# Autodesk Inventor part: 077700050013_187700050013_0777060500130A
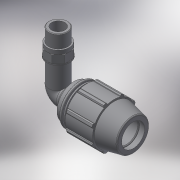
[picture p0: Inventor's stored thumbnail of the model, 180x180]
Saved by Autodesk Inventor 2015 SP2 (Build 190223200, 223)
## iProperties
Created: 2017-02
Part Number: 077700050013_187700050013_0777060500130A
Material: Generic
Description: PLASSON 90° ELBOW MALE WITH INTEGRAL BRASS THREAD 50-1.1/4"
Document SubType Name: Modeling
Designer: KIM
Mass: 174.249 g
Surface Area: 431.906 cm^2
Volume: 174.249 cm^3
Density: 1 g/cm^3
Appearance: Default
Author: KIM
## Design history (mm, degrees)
derived "07770.ipt"
feature "Solid1::07770.ipt"
tag "TaggingFeature1"
body "Solid1"
other parameters: "d4" = 12, "d5" = 36, "d7" = 96, "d9" = 20.57143, "d11" = 4.8, "d13" = 120 deg, "d15" = 12 deg, "d16" = 83.52, "d18" = 2.5, "d19" = 35 deg, "d20" = 17.5 deg, "d21" = 89.28, "d23" = 0, "d25" = 360 deg, "d27" = 1.92, "d33" = 1, "d42" = 53.28, "d43" = 2.88, "d46" = 1.5, "d51" = 144, "d68" = 9.6, "d72" = 97, "d73" = 41.91, "d74" = 22, "d75" = 48.1965, "d76" = 29.337, "d79" = 16.764, "d80" = 1.2573, "d83" = 0, "d84" = 0, "d91" = 72, "d93" = 93, "d94" = 41.91, "d95" = 29.337, "d96" = 9.6, "d97" = 50 deg, "d98" = 2.4, "d99" = 81.0144, "d100" = 2.4, "d101" = 2.4, "d105" = 2.2, "d106" = 50.292, "d107" = 22, "d108" = 13.2, "d109" = 0, "E_" = 96, "A_" = 144, "l_" = 93, "l_2" = 22, "A_1" = 97, "R_" = 41.91
